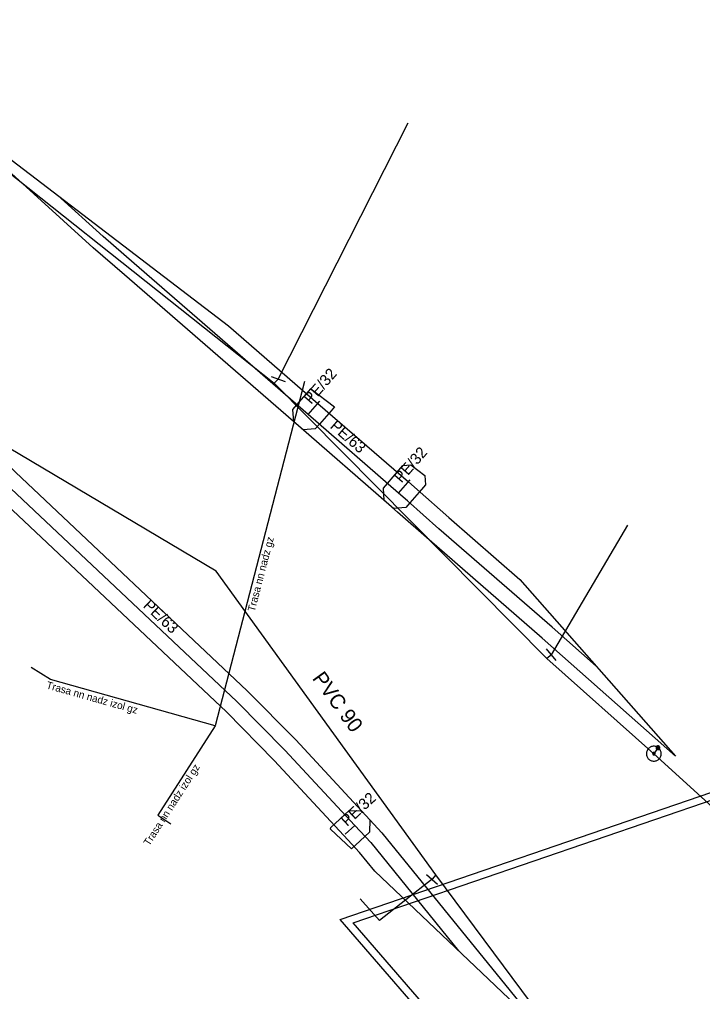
# Model space of a CAD drawing. Extents: x -743072 to -742584, y -978827 to -978325.
# Drawn here: x -742919.2 to -742873.3, y -978491.4 to -978426 of the extents above; entities that cross this region are included whole.
import ezdxf

# ---------------------------------------------------------------- set-up
doc = ezdxf.new("R2010")
doc.units = 0
for name, color, linetype in [('IS_CETIN_sdělovací kabel_nadz', 7, 'Continuous'), ('IS_CEZ_NN_nadz', 7, 'Continuous'), ('IS_GasNet_ochr pasmo', 7, 'Continuous'), ('IS_GasNet_plyn STL', 7, 'Continuous'), ('IS_Obec_kabel VO_nadz', 7, 'Continuous'), ('IS_popis_CEZ', 7, 'Continuous'), ('IS_popis_GasNet', 7, 'Continuous'), ('IS_popis_ScVK', 7, 'Continuous'), ('IS_ScVK_Kanal_dest', 7, 'Continuous'), ('IS_ScVK_Vodovod', 7, 'Continuous')]:
    doc.layers.add(name, color=color, linetype=linetype)

msp = doc.modelspace()

# ---------------------------------------------------------------- linework, layer by layer
at = {"layer": 'IS_CETIN_sdělovací kabel_nadz'}
msp.add_lwpolyline([(-742799.79, -978544.98), (-742828.86, -978567.32), (-742867.05, -978521.91), (-742897.64, -978486.54), (-742872.63, -978477.97), (-742862.09, -978471.14)], dxfattribs=at)
at = {"layer": 'IS_CEZ_NN_nadz'}
for points in [[(-742900.04, -978450.33), (-742906.06, -978473.51)], [(-742906.06, -978473.51), (-742917.153, -978470.395), (-742918.451, -978469.581)], [(-742906.06, -978473.51), (-742909.91, -978479.51), (-742909.04, -978480.111)]]:
    msp.add_lwpolyline(points, dxfattribs=at)
at = {"layer": 'IS_GasNet_ochr pasmo'}
for points in [[(-742914.264, -978441.318), (-742926.022, -978430.64), (-742905.159, -978446.574), (-742899.146, -978451.799), (-742893.056, -978457.091), (-742892.46, -978457.608), (-742890.34, -978459.488), (-742885.549, -978463.651), (-742875.072, -978475.552), (-742884.039, -978467.612), (-742891.66, -978460.992), (-742893.78, -978459.112), (-742894.368, -978458.601), (-742900.458, -978453.309), (-742912.165, -978443.135)], [(-742899.612, -978450.81), (-742898.02, -978452.026), (-742898.258, -978452.3), (-742899.047, -978453.209), (-742899.318, -978453.522), (-742900.144, -978453.581), (-742900.457, -978453.309), (-742900.77, -978453.038), (-742900.829, -978452.212), (-742900.557, -978451.899), (-742899.768, -978450.99)], [(-742892.89, -978455.944), (-742891.95, -978456.662), (-742891.906, -978457.293), (-742892.178, -978457.606), (-742892.957, -978458.502), (-742893.229, -978458.815), (-742894.055, -978458.873), (-742894.368, -978458.601), (-742894.681, -978458.329), (-742894.739, -978457.503), (-742894.467, -978457.19), (-742893.688, -978456.294), (-742893.416, -978455.981)], [(-742896.892, -978481.795), (-742898.288, -978480.469), (-742898.284, -978480.358), (-742897.98, -978480.077), (-742897.339, -978479.483), (-742897.035, -978479.201), (-742896.207, -978479.232), (-742895.926, -978479.536), (-742895.644, -978479.84), (-742895.675, -978480.668), (-742895.979, -978480.949), (-742896.62, -978481.543)]]:
    msp.add_lwpolyline(points, close=True, dxfattribs=at)
msp.add_lwpolyline([(-742884.489, -978493.578), (-742895.323, -978483.286), (-742896.346, -978482.026), (-742897.393, -978480.896), (-742902.083, -978475.831), (-742905.299, -978472.575), (-742920.881, -978457.883), (-742923.792, -978455.061), (-742924.401, -978454.471), (-742929.291, -978451.39), (-742931.913, -978450.512), (-742941.288, -978445.265), (-742928.429, -978449.57), (-742923.159, -978452.889), (-742922.4, -978453.625), (-742919.499, -978456.437), (-742903.901, -978471.145), (-742900.637, -978474.449), (-742895.925, -978479.536), (-742894.834, -978480.714), (-742882.031, -978496.481)], dxfattribs=at)
at = {"layer": 'IS_GasNet_plyn STL'}
for points in [[(-742880.405, -978469.494), (-742883.38, -978466.86), (-742891, -978460.24), (-742893.12, -978458.36), (-742893.712, -978457.846), (-742899.802, -978452.554), (-742911.51, -978442.38), (-742913.6, -978440.57), (-742916.664, -978437.788)], [(-742936.599, -978447.889), (-742928.86, -978450.48), (-742923.78, -978453.68), (-742923.096, -978454.343), (-742920.19, -978457.16), (-742904.6, -978471.86), (-742901.36, -978475.14), (-742896.659, -978480.216), (-742895.59, -978481.37), (-742889.684, -978488.643)], [(-742899.802, -978452.554), (-742899.013, -978451.645)], [(-742893.712, -978457.846), (-742892.933, -978456.95)], [(-742896.659, -978480.216), (-742897.3, -978480.81)]]:
    msp.add_lwpolyline(points, dxfattribs=at)
at = {"layer": 'IS_Obec_kabel VO_nadz'}
msp.add_lwpolyline([(-742800.095, -978544.584), (-742828.785, -978566.632), (-742866.67, -978521.586), (-742896.777, -978486.773), (-742872.41, -978478.423), (-742861.818, -978471.56)], dxfattribs=at)
at = {"layer": 'IS_ScVK_Kanal_dest'}
for points in [[(-742902.077, -978450.432), (-742901.82, -978450.16)], [(-742883.43, -978468.719), (-742883.738, -978468.975)], [(-742876.254, -978474.982), (-742876.53, -978475.383)], [(-742891.202, -978483.542), (-742891.46, -978483.84)]]:
    msp.add_lwpolyline(points, dxfattribs=at)
at = {"layer": 'IS_ScVK_Vodovod'}
for points in [[(-742977.649, -978388.53), (-742976.664, -978389.595), (-742974.357, -978391.436), (-742948.728, -978413.286), (-742927.308, -978430.422), (-742902.077, -978450.432), (-742883.738, -978468.975), (-742876.53, -978475.383)], [(-742901.82, -978450.16), (-742893.072, -978432.916)], [(-742902.291, -978449.992), (-742901.349, -978450.328)], [(-742866.026, -978515.027), (-742875.324, -978505.832), (-742881.523, -978496.585), (-742891.202, -978483.542), (-742905.997, -978463.103), (-742924.708, -978451.984), (-742925.299, -978451.559), (-742925.477, -978451.431)], [(-742883.43, -978468.719), (-742878.274, -978459.998)], [(-742883.11, -978469.104), (-742883.748, -978468.333)], [(-742876.03, -978475.383), (-742876.033, -978475.331), (-742876.041, -978475.279), (-742876.055, -978475.229), (-742876.073, -978475.18), (-742876.097, -978475.133), (-742876.126, -978475.089), (-742876.159, -978475.049), (-742876.196, -978475.012), (-742876.236, -978474.979), (-742876.28, -978474.95), (-742876.327, -978474.926), (-742876.376, -978474.908), (-742876.426, -978474.894), (-742876.478, -978474.886), (-742876.53, -978474.883), (-742876.582, -978474.886), (-742876.634, -978474.894), (-742876.685, -978474.908), (-742876.733, -978474.926), (-742876.78, -978474.95), (-742876.824, -978474.979), (-742876.865, -978475.012), (-742876.902, -978475.049), (-742876.935, -978475.089), (-742876.963, -978475.133), (-742876.987, -978475.18), (-742877.006, -978475.229), (-742877.019, -978475.279), (-742877.027, -978475.331), (-742877.03, -978475.383), (-742877.027, -978475.435), (-742877.019, -978475.487), (-742877.006, -978475.538), (-742876.987, -978475.586), (-742876.963, -978475.633), (-742876.935, -978475.677), (-742876.902, -978475.718), (-742876.865, -978475.755), (-742876.824, -978475.788), (-742876.78, -978475.816), (-742876.733, -978475.84), (-742876.685, -978475.859), (-742876.634, -978475.872), (-742876.582, -978475.88), (-742876.53, -978475.883), (-742876.478, -978475.88), (-742876.426, -978475.872), (-742876.376, -978475.859), (-742876.327, -978475.84), (-742876.28, -978475.816), (-742876.236, -978475.788), (-742876.196, -978475.755), (-742876.159, -978475.718), (-742876.126, -978475.677), (-742876.097, -978475.633), (-742876.073, -978475.586), (-742876.055, -978475.538), (-742876.041, -978475.487), (-742876.033, -978475.435), (-742876.03, -978475.383)], [(-742876.38, -978474.982), (-742876.38, -978474.995), (-742876.377, -978475.008), (-742876.375, -978475.021), (-742876.37, -978475.033), (-742876.364, -978475.045), (-742876.357, -978475.056), (-742876.348, -978475.066), (-742876.338, -978475.076), (-742876.328, -978475.084), (-742876.318, -978475.091), (-742876.306, -978475.097), (-742876.294, -978475.102), (-742876.281, -978475.105), (-742876.267, -978475.107), (-742876.255, -978475.109), (-742876.242, -978475.108), (-742876.228, -978475.106), (-742876.216, -978475.103), (-742876.203, -978475.098), (-742876.191, -978475.092), (-742876.181, -978475.085), (-742876.171, -978475.077), (-742876.161, -978475.067), (-742876.152, -978475.057), (-742876.146, -978475.046), (-742876.14, -978475.034), (-742876.135, -978475.022), (-742876.132, -978475.009), (-742876.13, -978474.996), (-742876.127, -978474.983), (-742876.129, -978474.97), (-742876.13, -978474.957), (-742876.134, -978474.944), (-742876.139, -978474.932), (-742876.144, -978474.92), (-742876.152, -978474.909), (-742876.159, -978474.899), (-742876.169, -978474.889), (-742876.179, -978474.881), (-742876.191, -978474.874), (-742876.203, -978474.868), (-742876.215, -978474.863), (-742876.228, -978474.86), (-742876.24, -978474.858), (-742876.254, -978474.857), (-742876.267, -978474.857), (-742876.279, -978474.859), (-742876.293, -978474.862), (-742876.304, -978474.867), (-742876.316, -978474.873), (-742876.328, -978474.88), (-742876.338, -978474.888), (-742876.348, -978474.898), (-742876.355, -978474.908), (-742876.363, -978474.919), (-742876.369, -978474.931), (-742876.374, -978474.943), (-742876.377, -978474.956), (-742876.379, -978474.969), (-742876.38, -978474.982)], [(-742876.36, -978474.982), (-742876.36, -978474.993), (-742876.358, -978475.004), (-742876.355, -978475.015), (-742876.352, -978475.025), (-742876.347, -978475.035), (-742876.341, -978475.044), (-742876.333, -978475.053), (-742876.326, -978475.061), (-742876.316, -978475.068), (-742876.308, -978475.074), (-742876.298, -978475.079), (-742876.288, -978475.083), (-742876.277, -978475.086), (-742876.266, -978475.089), (-742876.255, -978475.089), (-742876.244, -978475.089), (-742876.233, -978475.087), (-742876.222, -978475.084), (-742876.212, -978475.08), (-742876.201, -978475.075), (-742876.193, -978475.069), (-742876.184, -978475.062), (-742876.176, -978475.054), (-742876.169, -978475.045), (-742876.163, -978475.036), (-742876.157, -978475.026), (-742876.154, -978475.016), (-742876.151, -978475.005), (-742876.149, -978474.994), (-742876.147, -978474.983), (-742876.147, -978474.972), (-742876.149, -978474.961), (-742876.152, -978474.95), (-742876.157, -978474.94), (-742876.162, -978474.93), (-742876.168, -978474.921), (-742876.174, -978474.912), (-742876.183, -978474.904), (-742876.191, -978474.897), (-742876.201, -978474.891), (-742876.211, -978474.886), (-742876.22, -978474.882), (-742876.232, -978474.879), (-742876.242, -978474.877), (-742876.254, -978474.877), (-742876.265, -978474.876), (-742876.276, -978474.878), (-742876.287, -978474.881), (-742876.296, -978474.885), (-742876.306, -978474.89), (-742876.316, -978474.896), (-742876.325, -978474.903), (-742876.333, -978474.911), (-742876.34, -978474.92), (-742876.345, -978474.929), (-742876.35, -978474.939), (-742876.355, -978474.949), (-742876.358, -978474.96), (-742876.36, -978474.971), (-742876.36, -978474.982)], [(-742876.341, -978474.982), (-742876.341, -978474.991), (-742876.34, -978475), (-742876.337, -978475.009), (-742876.333, -978475.017), (-742876.33, -978475.025), (-742876.325, -978475.033), (-742876.318, -978475.04), (-742876.313, -978475.046), (-742876.306, -978475.052), (-742876.298, -978475.057), (-742876.289, -978475.061), (-742876.282, -978475.064), (-742876.272, -978475.067), (-742876.264, -978475.068), (-742876.255, -978475.07), (-742876.245, -978475.069), (-742876.237, -978475.068), (-742876.228, -978475.065), (-742876.22, -978475.062), (-742876.212, -978475.058), (-742876.203, -978475.053), (-742876.196, -978475.047), (-742876.191, -978475.041), (-742876.184, -978475.034), (-742876.179, -978475.026), (-742876.176, -978475.018), (-742876.173, -978475.01), (-742876.169, -978475.001), (-742876.169, -978474.992), (-742876.166, -978474.983), (-742876.168, -978474.974), (-742876.169, -978474.965), (-742876.171, -978474.956), (-742876.174, -978474.948), (-742876.179, -978474.94), (-742876.184, -978474.932), (-742876.19, -978474.925), (-742876.196, -978474.919), (-742876.203, -978474.913), (-742876.211, -978474.908), (-742876.218, -978474.904), (-742876.227, -978474.901), (-742876.235, -978474.898), (-742876.245, -978474.897), (-742876.254, -978474.896), (-742876.262, -978474.896), (-742876.272, -978474.897), (-742876.281, -978474.9), (-742876.289, -978474.903), (-742876.296, -978474.907), (-742876.304, -978474.912), (-742876.311, -978474.918), (-742876.318, -978474.924), (-742876.323, -978474.931), (-742876.328, -978474.939), (-742876.333, -978474.947), (-742876.336, -978474.955), (-742876.338, -978474.964), (-742876.34, -978474.973), (-742876.341, -978474.982)], [(-742876.321, -978474.982), (-742876.321, -978474.989), (-742876.32, -978474.996), (-742876.318, -978475.003), (-742876.316, -978475.009), (-742876.313, -978475.015), (-742876.309, -978475.021), (-742876.304, -978475.027), (-742876.299, -978475.032), (-742876.294, -978475.036), (-742876.288, -978475.04), (-742876.282, -978475.043), (-742876.276, -978475.046), (-742876.269, -978475.047), (-742876.262, -978475.05), (-742876.255, -978475.05), (-742876.247, -978475.05), (-742876.24, -978475.048), (-742876.233, -978475.047), (-742876.228, -978475.044), (-742876.22, -978475.041), (-742876.216, -978475.037), (-742876.21, -978475.033), (-742876.205, -978475.028), (-742876.201, -978475.022), (-742876.196, -978475.016), (-742876.193, -978475.01), (-742876.191, -978475.004), (-742876.189, -978474.997), (-742876.188, -978474.99), (-742876.186, -978474.983), (-742876.186, -978474.976), (-742876.188, -978474.969), (-742876.19, -978474.962), (-742876.193, -978474.956), (-742876.196, -978474.949), (-742876.2, -978474.944), (-742876.203, -978474.938), (-742876.208, -978474.933), (-742876.215, -978474.929), (-742876.22, -978474.925), (-742876.227, -978474.922), (-742876.233, -978474.919), (-742876.24, -978474.917), (-742876.247, -978474.916), (-742876.254, -978474.916), (-742876.261, -978474.916), (-742876.267, -978474.916), (-742876.274, -978474.918), (-742876.281, -978474.921), (-742876.287, -978474.924), (-742876.293, -978474.928), (-742876.299, -978474.932), (-742876.304, -978474.937), (-742876.308, -978474.943), (-742876.311, -978474.948), (-742876.315, -978474.955), (-742876.318, -978474.961), (-742876.318, -978474.968), (-742876.321, -978474.975), (-742876.321, -978474.982)], [(-742876.301, -978474.982), (-742876.301, -978474.987), (-742876.301, -978474.992), (-742876.299, -978474.997), (-742876.298, -978475.001), (-742876.296, -978475.006), (-742876.293, -978475.01), (-742876.289, -978475.013), (-742876.286, -978475.017), (-742876.282, -978475.02), (-742876.279, -978475.023), (-742876.274, -978475.025), (-742876.269, -978475.027), (-742876.265, -978475.028), (-742876.26, -978475.03), (-742876.255, -978475.03), (-742876.25, -978475.03), (-742876.245, -978475.029), (-742876.24, -978475.028), (-742876.235, -978475.026), (-742876.23, -978475.024), (-742876.227, -978475.021), (-742876.223, -978475.018), (-742876.22, -978475.014), (-742876.217, -978475.011), (-742876.213, -978475.007), (-742876.212, -978475.002), (-742876.21, -978474.998), (-742876.208, -978474.993), (-742876.208, -978474.988), (-742876.206, -978474.983), (-742876.206, -978474.978), (-742876.208, -978474.973), (-742876.208, -978474.968), (-742876.211, -978474.964), (-742876.213, -978474.959), (-742876.216, -978474.955), (-742876.218, -978474.951), (-742876.222, -978474.948), (-742876.225, -978474.945), (-742876.23, -978474.942), (-742876.235, -978474.94), (-742876.239, -978474.938), (-742876.244, -978474.937), (-742876.249, -978474.936), (-742876.254, -978474.936), (-742876.259, -978474.936), (-742876.264, -978474.937), (-742876.269, -978474.937), (-742876.272, -978474.939), (-742876.277, -978474.941), (-742876.282, -978474.944), (-742876.284, -978474.947), (-742876.289, -978474.95), (-742876.291, -978474.954), (-742876.294, -978474.958), (-742876.296, -978474.963), (-742876.299, -978474.967), (-742876.299, -978474.972), (-742876.301, -978474.977), (-742876.301, -978474.982)], [(-742876.281, -978474.982), (-742876.281, -978474.985), (-742876.282, -978474.988), (-742876.281, -978474.99), (-742876.279, -978474.993), (-742876.279, -978474.996), (-742876.277, -978474.998), (-742876.274, -978475), (-742876.272, -978475.002), (-742876.271, -978475.004), (-742876.269, -978475.006), (-742876.266, -978475.008), (-742876.262, -978475.009), (-742876.261, -978475.009), (-742876.257, -978475.01), (-742876.255, -978475.01), (-742876.252, -978475.01), (-742876.249, -978475.01), (-742876.245, -978475.009), (-742876.244, -978475.008), (-742876.24, -978475.007), (-742876.239, -978475.005), (-742876.235, -978475.003), (-742876.233, -978475.001), (-742876.233, -978474.999), (-742876.23, -978474.997), (-742876.23, -978474.994), (-742876.228, -978474.991), (-742876.228, -978474.989), (-742876.227, -978474.986), (-742876.225, -978474.983), (-742876.227, -978474.98), (-742876.227, -978474.977), (-742876.228, -978474.974), (-742876.228, -978474.972), (-742876.23, -978474.969), (-742876.232, -978474.967), (-742876.233, -978474.964), (-742876.235, -978474.962), (-742876.238, -978474.961), (-742876.24, -978474.959), (-742876.242, -978474.958), (-742876.245, -978474.957), (-742876.247, -978474.956), (-742876.25, -978474.956), (-742876.254, -978474.955), (-742876.257, -978474.956), (-742876.26, -978474.955), (-742876.262, -978474.957), (-742876.265, -978474.957), (-742876.267, -978474.958), (-742876.269, -978474.96), (-742876.272, -978474.961), (-742876.274, -978474.963), (-742876.276, -978474.966), (-742876.277, -978474.968), (-742876.279, -978474.971), (-742876.279, -978474.973), (-742876.281, -978474.976), (-742876.281, -978474.979), (-742876.281, -978474.982)], [(-742876.262, -978474.982), (-742876.262, -978474.984), (-742876.262, -978474.984), (-742876.261, -978474.984), (-742876.261, -978474.986), (-742876.262, -978474.987), (-742876.26, -978474.987), (-742876.26, -978474.987), (-742876.26, -978474.989), (-742876.26, -978474.989), (-742876.259, -978474.99), (-742876.257, -978474.99), (-742876.257, -978474.99), (-742876.257, -978474.991), (-742876.255, -978474.991), (-742876.255, -978474.991), (-742876.254, -978474.991), (-742876.252, -978474.991), (-742876.252, -978474.99), (-742876.252, -978474.99), (-742876.25, -978474.99), (-742876.25, -978474.989), (-742876.25, -978474.989), (-742876.249, -978474.988), (-742876.249, -978474.988), (-742876.247, -978474.987), (-742876.247, -978474.986), (-742876.245, -978474.985), (-742876.245, -978474.985), (-742876.245, -978474.984), (-742876.245, -978474.983), (-742876.245, -978474.982), (-742876.245, -978474.981), (-742876.245, -978474.981), (-742876.247, -978474.98), (-742876.247, -978474.979), (-742876.247, -978474.978), (-742876.247, -978474.978), (-742876.249, -978474.977), (-742876.249, -978474.977), (-742876.25, -978474.976), (-742876.25, -978474.976), (-742876.252, -978474.975), (-742876.252, -978474.975), (-742876.252, -978474.975), (-742876.254, -978474.975), (-742876.255, -978474.975), (-742876.255, -978474.975), (-742876.255, -978474.975), (-742876.257, -978474.976), (-742876.257, -978474.975), (-742876.259, -978474.977), (-742876.259, -978474.977), (-742876.26, -978474.977), (-742876.26, -978474.977), (-742876.261, -978474.979), (-742876.261, -978474.98), (-742876.261, -978474.981), (-742876.262, -978474.981), (-742876.262, -978474.982), (-742876.262, -978474.982)], [(-742876.448, -978475.383), (-742876.448, -978475.374), (-742876.45, -978475.366), (-742876.452, -978475.358), (-742876.455, -978475.35), (-742876.459, -978475.342), (-742876.464, -978475.335), (-742876.469, -978475.328), (-742876.475, -978475.322), (-742876.482, -978475.317), (-742876.489, -978475.312), (-742876.497, -978475.308), (-742876.505, -978475.305), (-742876.513, -978475.303), (-742876.521, -978475.301), (-742876.53, -978475.301), (-742876.539, -978475.301), (-742876.547, -978475.303), (-742876.555, -978475.305), (-742876.563, -978475.308), (-742876.571, -978475.312), (-742876.578, -978475.317), (-742876.585, -978475.322), (-742876.591, -978475.328), (-742876.597, -978475.335), (-742876.601, -978475.342), (-742876.605, -978475.35), (-742876.608, -978475.358), (-742876.61, -978475.366), (-742876.612, -978475.374), (-742876.612, -978475.383), (-742876.612, -978475.392), (-742876.61, -978475.4), (-742876.608, -978475.408), (-742876.605, -978475.416), (-742876.601, -978475.424), (-742876.597, -978475.431), (-742876.591, -978475.438), (-742876.585, -978475.444), (-742876.578, -978475.45), (-742876.571, -978475.454), (-742876.563, -978475.458), (-742876.555, -978475.461), (-742876.547, -978475.463), (-742876.539, -978475.465), (-742876.53, -978475.465), (-742876.521, -978475.465), (-742876.513, -978475.463), (-742876.505, -978475.461), (-742876.497, -978475.458), (-742876.489, -978475.454), (-742876.482, -978475.45), (-742876.475, -978475.444), (-742876.469, -978475.438), (-742876.464, -978475.431), (-742876.459, -978475.424), (-742876.455, -978475.416), (-742876.452, -978475.408), (-742876.45, -978475.4), (-742876.448, -978475.392), (-742876.448, -978475.383)], [(-742876.53, -978475.383), (-742870.143, -978481.198), (-742836.467, -978520.3), (-742824.743, -978534.055), (-742817.583, -978544.51)], [(-742891.836, -978483.51), (-742891.084, -978484.169)], [(-742891.46, -978483.84), (-742894.998, -978486.612), (-742896.291, -978485.151)]]:
    msp.add_lwpolyline(points, dxfattribs=at)

# ---------------------------------------------------------------- texts
at = {"layer": 'IS_popis_CEZ'}
for s, rotation, p in [('Trasa nn nadz gz', 75.44153, (-742903.4, -978465.853)), ('Trasa nn nadz izol gz', 344.31485, (-742917.464, -978470.983)), ('Trasa nn nadz izol gz', 57.31306, (-742910.497, -978481.628))]:
    msp.add_text(s, height=0.5, rotation=rotation, dxfattribs=at).set_placement(p)
at = {"layer": 'IS_popis_GasNet'}
for s, rotation, p in [('PE/32', 49.04245, (-742899.607, -978451.9)), ('PE/63', 319.01048, (-742898.38, -978453.416)), ('PE/32', 48.99566, (-742893.523, -978457.198)), ('PE/63', 316.68302, (-742910.956, -978465.478)), ('PE/32', 42.82056, (-742897.18, -978480.313))]:
    msp.add_text(s, height=0.75, rotation=rotation, dxfattribs=at).set_placement(p)
at = {"layer": 'IS_popis_ScVK'}
msp.add_text('PVC 90', height=1, rotation=306, dxfattribs=at).set_placement((-742899.56, -978470.315))

doc.saveas('drawing.dxf')
